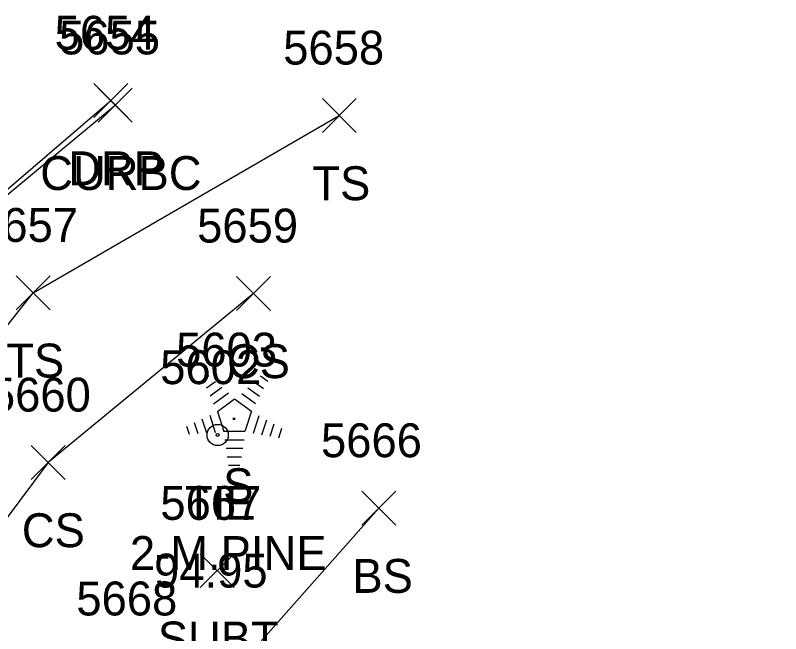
# Model space of a CAD drawing. Extents: x 1505656 to 1508446, y 700805 to 703031.
# Drawn here: x 1508306.98 to 1508352.1, y 700945.56 to 700982.04 of the extents above; entities that cross this region are included whole.
import ezdxf

# ---------------------------------------------------------------- set-up
doc = ezdxf.new("R2010")
doc.units = 0
for name, color, linetype in [('C_A', 7, 'Continuous'), ('C_C', 7, 'Continuous'), ('C_I', 7, 'Continuous'), ('CBP', 7, 'Continuous'), ('L_A', 7, 'Continuous'), ('L_C', 7, 'Continuous'), ('L_I', 7, 'Continuous'), ('L_TIC', 7, 'Continuous'), ('LELB', 7, 'Continuous'), ('LTC', 7, 'Continuous'), ('R_A', 7, 'Continuous'), ('R_I', 7, 'Continuous'), ('R_TIC', 7, 'Continuous'), ('RC', 7, 'Continuous'), ('RDP', 7, 'Continuous'), ('U_A', 7, 'Continuous'), ('U_I', 7, 'Continuous'), ('U_TIC', 7, 'Continuous')]:
    doc.layers.add(name, color=color, linetype=linetype)

msp = doc.modelspace()

# ---------------------------------------------------------------- linework, layer by layer
at = {"layer": 'CBP'}
for radius in [0.625, 0.0833]:
    msp.add_circle((1508318.904, 700957.284), radius, dxfattribs=at)
at = {"layer": 'L_TIC'}
for points in [[(1508325.077, 700975.136), (1508327.077, 700977.136)], [(1508327.077, 700975.136), (1508325.077, 700977.136)], [(1508307.033, 700964.674), (1508309.033, 700966.674)], [(1508309.033, 700964.674), (1508307.033, 700966.674)], [(1508320.011, 700964.637), (1508322.011, 700966.637)], [(1508322.011, 700964.637), (1508320.011, 700966.637)], [(1508307.92, 700954.664), (1508309.92, 700956.664)], [(1508309.92, 700954.664), (1508307.92, 700956.664)], [(1508327.407, 700951.971), (1508329.407, 700953.971)], [(1508329.407, 700951.971), (1508327.407, 700953.971)]]:
    msp.add_lwpolyline(points, dxfattribs=at)
at = {"layer": 'LELB'}
for points in [[(1508341.921, 700881.505), (1508318.487, 700898.474), (1508297.499, 700911.925), (1508290.704, 700922.28), (1508289.386, 700937.943), (1508297.087, 700951.826), (1508308.033, 700965.674), (1508326.077, 700976.136)], [(1508321.011, 700965.637), (1508308.92, 700955.664), (1508300.485, 700944.382), (1508294.249, 700931.737), (1508304.207, 700920.508)], [(1508352.096, 700895.324), (1508330.819, 700915.733), (1508312.132, 700926.666), (1508317.186, 700940.29), (1508328.407, 700952.971)]]:
    msp.add_lwpolyline(points, dxfattribs=at)
at = {"layer": 'LTC'}
for p, q in [((1508318.037, 700960.528), (1508318.392, 700960.785)), ((1508321.436, 700960.768), (1508321.855, 700960.464)), ((1508318.247, 700960.062), (1508318.776, 700960.447)), ((1508321.065, 700960.42), (1508321.614, 700960.021)), ((1508318.457, 700959.597), (1508319.16, 700960.108)), ((1508318.666, 700959.131), (1508319.545, 700959.769)), ((1508320.694, 700960.072), (1508321.373, 700959.578)), ((1508318.891, 700958.676), (1508319.902, 700959.41)), ((1508319.902, 700959.41), (1508320.9, 700958.685)), ((1508320.322, 700959.723), (1508321.132, 700959.135)), ((1508318.436, 700958.457), (1508318.767, 700957.437)), ((1508318.891, 700958.676), (1508319.278, 700957.482)), ((1508320.9, 700958.685), (1508320.508, 700957.482)), ((1508321.337, 700958.415), (1508320.999, 700957.375)), ((1508317.525, 700958.024), (1508317.737, 700957.372)), ((1508317.981, 700958.24), (1508318.252, 700957.405)), ((1508321.782, 700958.164), (1508321.494, 700957.28)), ((1508317.07, 700957.807), (1508317.222, 700957.339)), ((1508320.508, 700957.482), (1508319.278, 700957.482)), ((1508322.226, 700957.914), (1508321.989, 700957.185)), ((1508322.67, 700957.664), (1508322.484, 700957.09)), ((1508320.47, 700956.982), (1508319.325, 700956.982)), ((1508320.386, 700956.482), (1508319.398, 700956.482)), ((1508320.302, 700955.982), (1508319.471, 700955.982)), ((1508320.219, 700955.482), (1508319.544, 700955.482))]:
    msp.add_line(p, q, dxfattribs=at)
at = {"layer": 'R_TIC'}
for points in [[(1508311.603, 700976.013), (1508313.603, 700978.013)], [(1508313.603, 700976.013), (1508311.603, 700978.013)], [(1508311.864, 700975.736), (1508313.864, 700977.736)], [(1508313.864, 700975.736), (1508311.864, 700977.736)]]:
    msp.add_lwpolyline(points, dxfattribs=at)
at = {"layer": 'RC'}
msp.add_lwpolyline([(1508285.71, 700920.134), (1508285.268, 700921.752), (1508283.921, 700940.396), (1508286.688, 700947.222), (1508291.345, 700954.183), (1508292.537, 700955.916), (1508293.345, 700957.102), (1508294.348, 700958.55), (1508299.61, 700965.749), (1508312.864, 700976.736)], dxfattribs=at)
at = {"layer": 'RDP'}
msp.add_lwpolyline([(1508294.312, 700958.636), (1508299.531, 700965.782), (1508312.603, 700977.013)], dxfattribs=at)
at = {"layer": 'U_TIC'}
for points in [[(1508317.882, 700948.277), (1508319.882, 700950.277)], [(1508319.882, 700948.277), (1508317.882, 700950.277)]]:
    msp.add_lwpolyline(points, dxfattribs=at)

# ---------------------------------------------------------------- texts
at = {"layer": 'C_A'}
msp.add_text('TIE', height=2, dxfattribs=at).set_placement((1508316.983, 700952.284))
at = {"layer": 'C_C'}
msp.add_text('94.95', height=2, dxfattribs=at).set_placement((1508315.156, 700948.284))
at = {"layer": 'C_I'}
msp.add_text('5602', height=2, dxfattribs=at).set_placement((1508315.518, 700960.284))
at = {"layer": 'L_A'}
for s, p in [('TS', (1508324.487, 700971.136)), ('TS', (1508306.443, 700960.674)), ('CS', (1508319.452, 700960.637)), ('S', (1508319.228, 700953.32)), ('CS', (1508307.361, 700950.664)), ('BS', (1508326.848, 700947.971))]:
    msp.add_text(s, height=2, dxfattribs=at).set_placement(p)
at = {"layer": 'L_C'}
msp.add_text('2-M.PINE', height=2, dxfattribs=at).set_placement((1508313.732, 700949.32))
at = {"layer": 'L_I'}
for s, p in [('5658', (1508322.77, 700979.136)), ('5657', (1508304.726, 700968.674)), ('5659', (1508317.696, 700968.637)), ('5603', (1508316.456, 700961.32)), ('5660', (1508305.479, 700958.664)), ('5666', (1508324.997, 700955.971))]:
    msp.add_text(s, height=2, dxfattribs=at).set_placement(p)
at = {"layer": 'LTC'}
msp.add_text('.', height=1.037, rotation=270, dxfattribs=at).set_placement((1508319.785, 700958.424))
at = {"layer": 'R_A'}
for s, p in [('CURBC', (1508308.447, 700971.736)), ('DRP', (1508310.091, 700972.013))]:
    msp.add_text(s, height=2, dxfattribs=at).set_placement(p)
at = {"layer": 'R_I'}
for s, p in [('5654', (1508309.296, 700980.013)), ('5655', (1508309.557, 700979.736))]:
    msp.add_text(s, height=2, dxfattribs=at).set_placement(p)
at = {"layer": 'U_A'}
msp.add_text('SUBT', height=2, dxfattribs=at).set_placement((1508315.379, 700944.277))
at = {"layer": 'U_I'}
for s, p in [('5667', (1508315.528, 700952.277)), ('5668', (1508310.575, 700946.637))]:
    msp.add_text(s, height=2, dxfattribs=at).set_placement(p)

doc.saveas('drawing.dxf')
